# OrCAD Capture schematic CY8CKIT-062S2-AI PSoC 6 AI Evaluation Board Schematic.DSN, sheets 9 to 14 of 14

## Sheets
9 11. QSPI Memory and RADAR Snsr: size A4
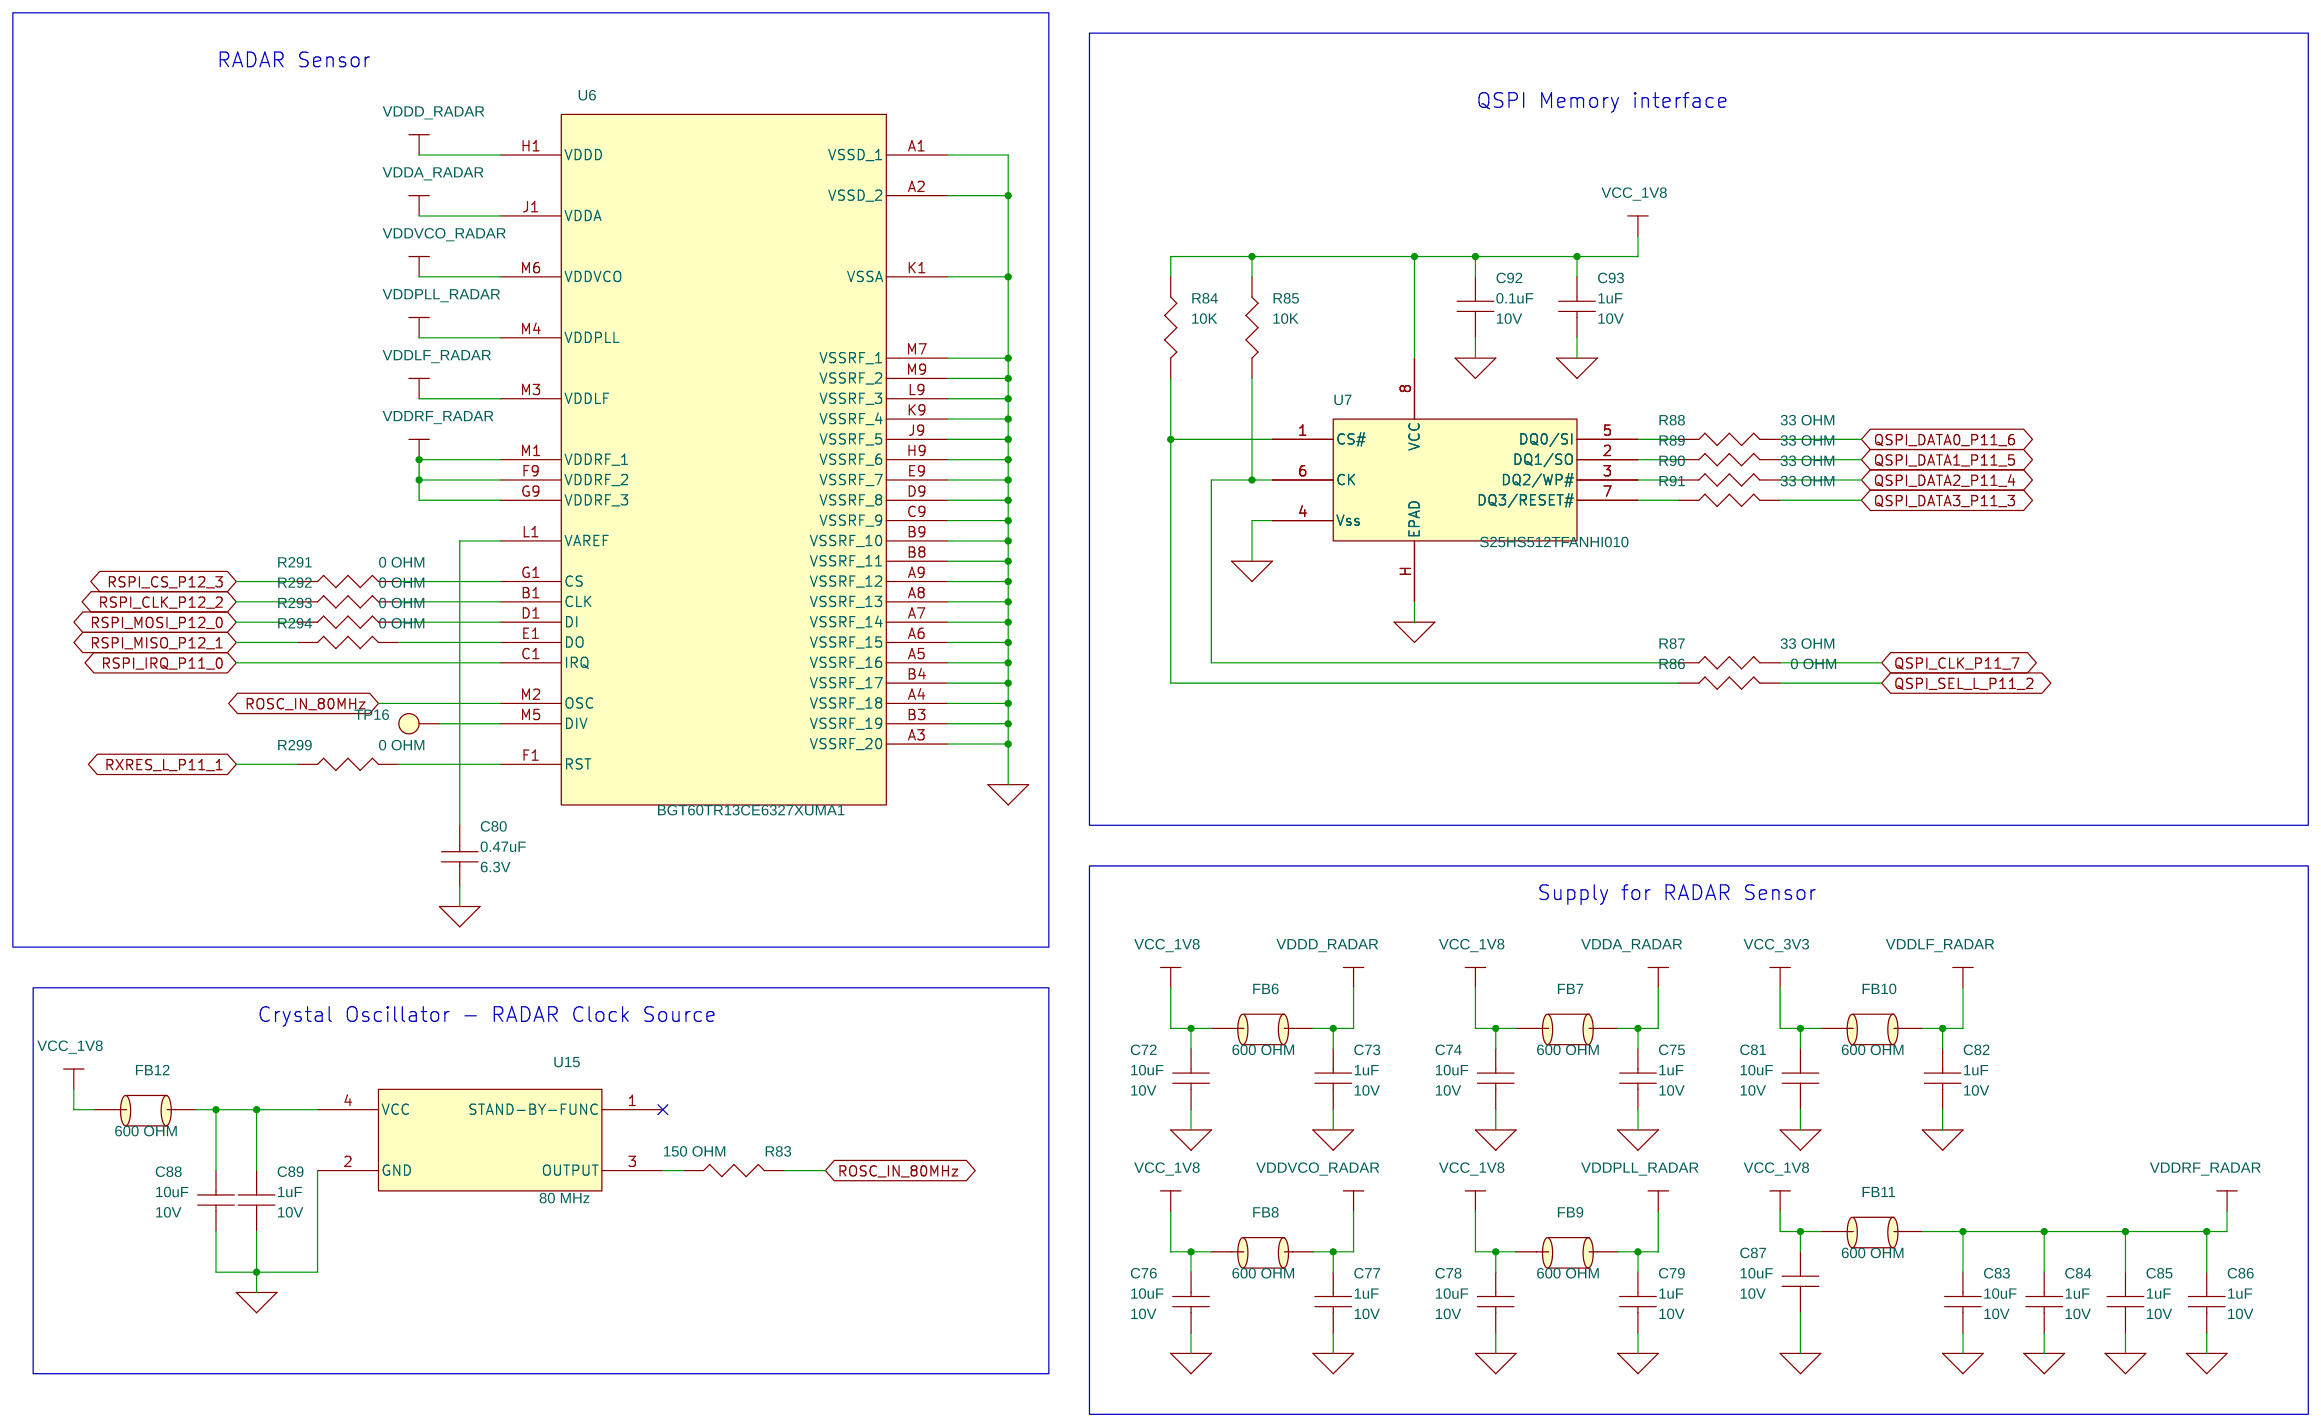
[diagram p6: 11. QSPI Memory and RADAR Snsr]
10 12.1YN Module Interface: size A4
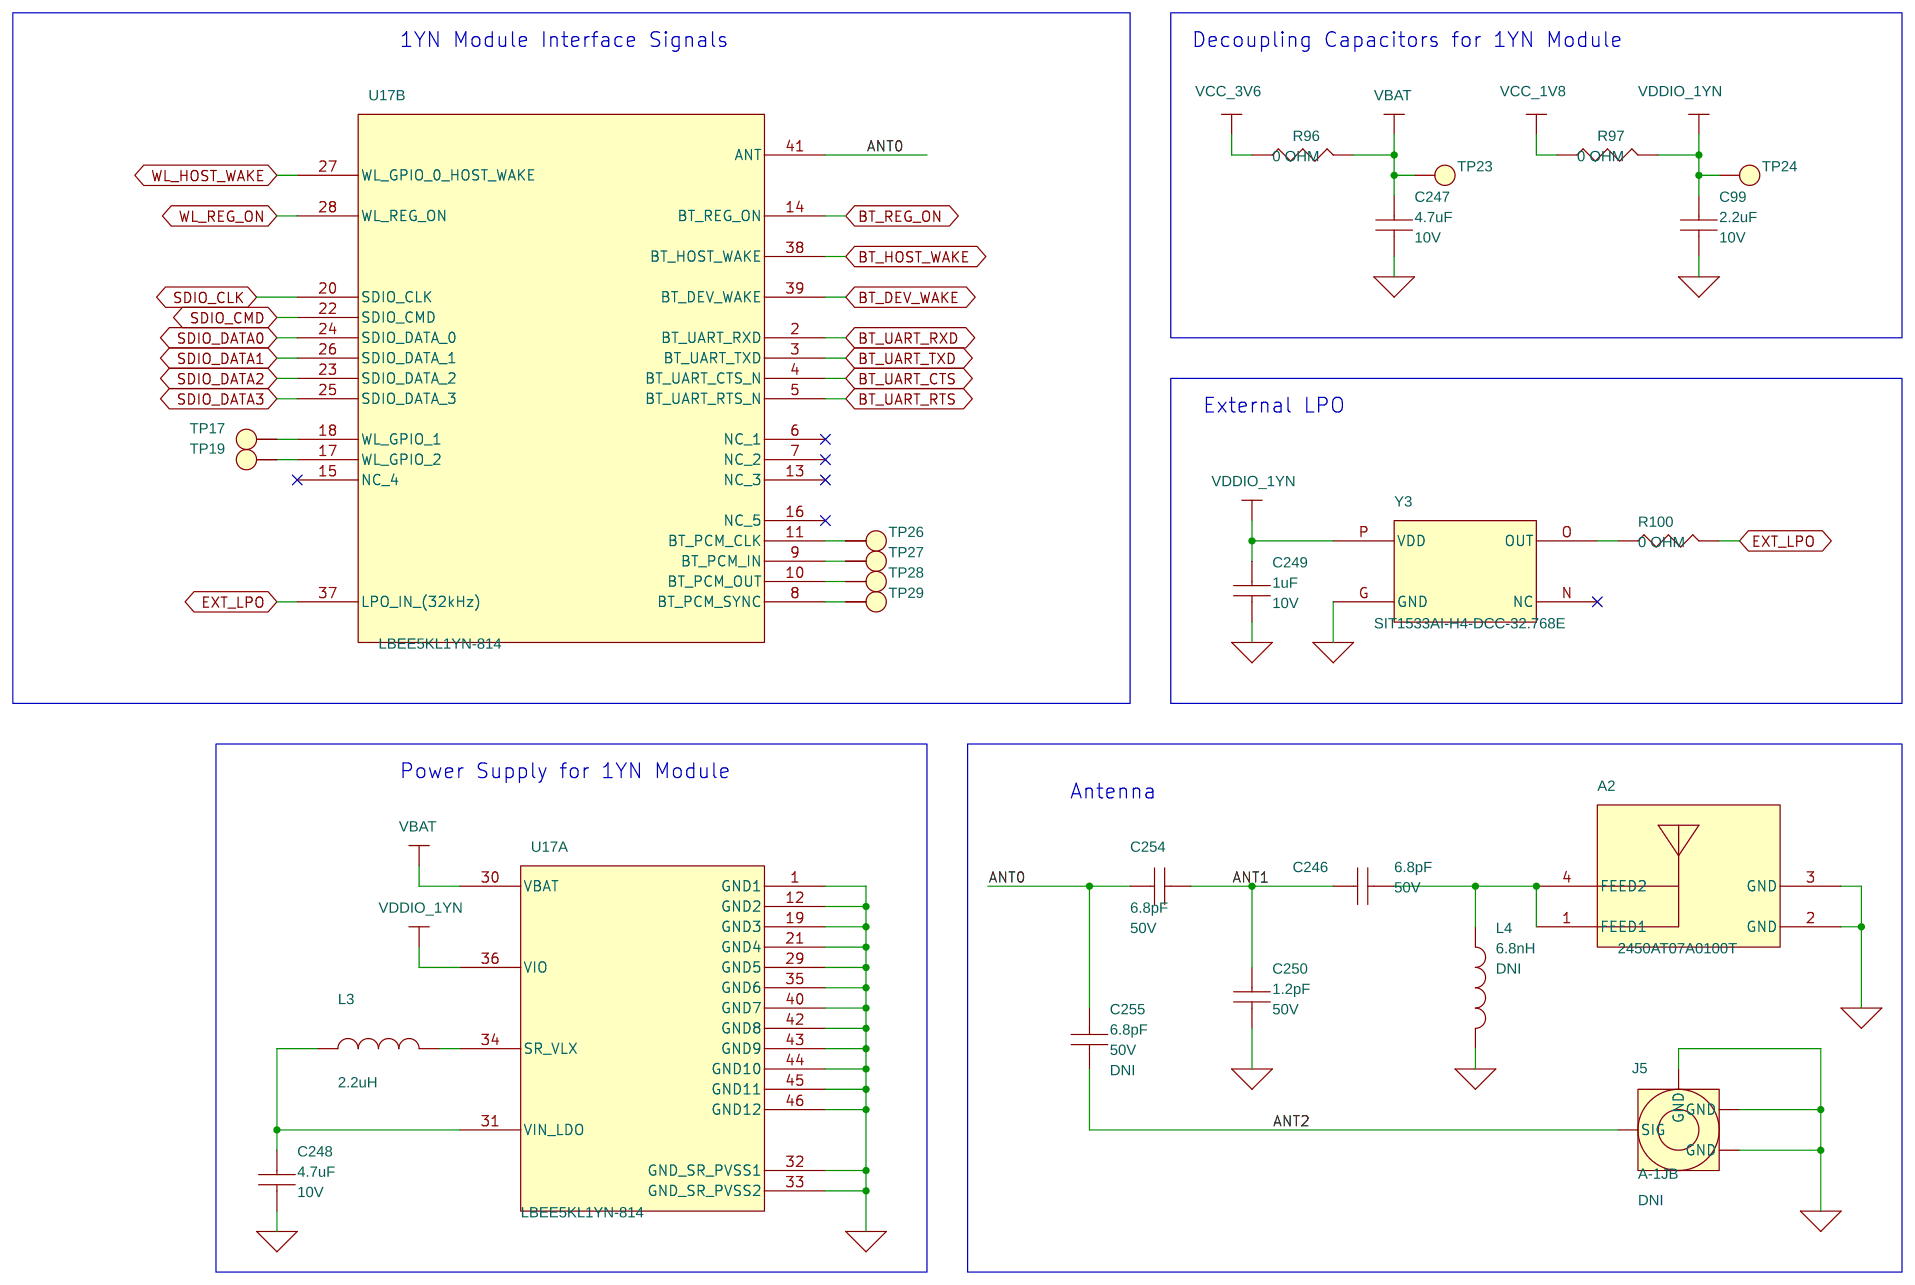
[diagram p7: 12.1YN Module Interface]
11 13. IO Expansion connectors: size A4
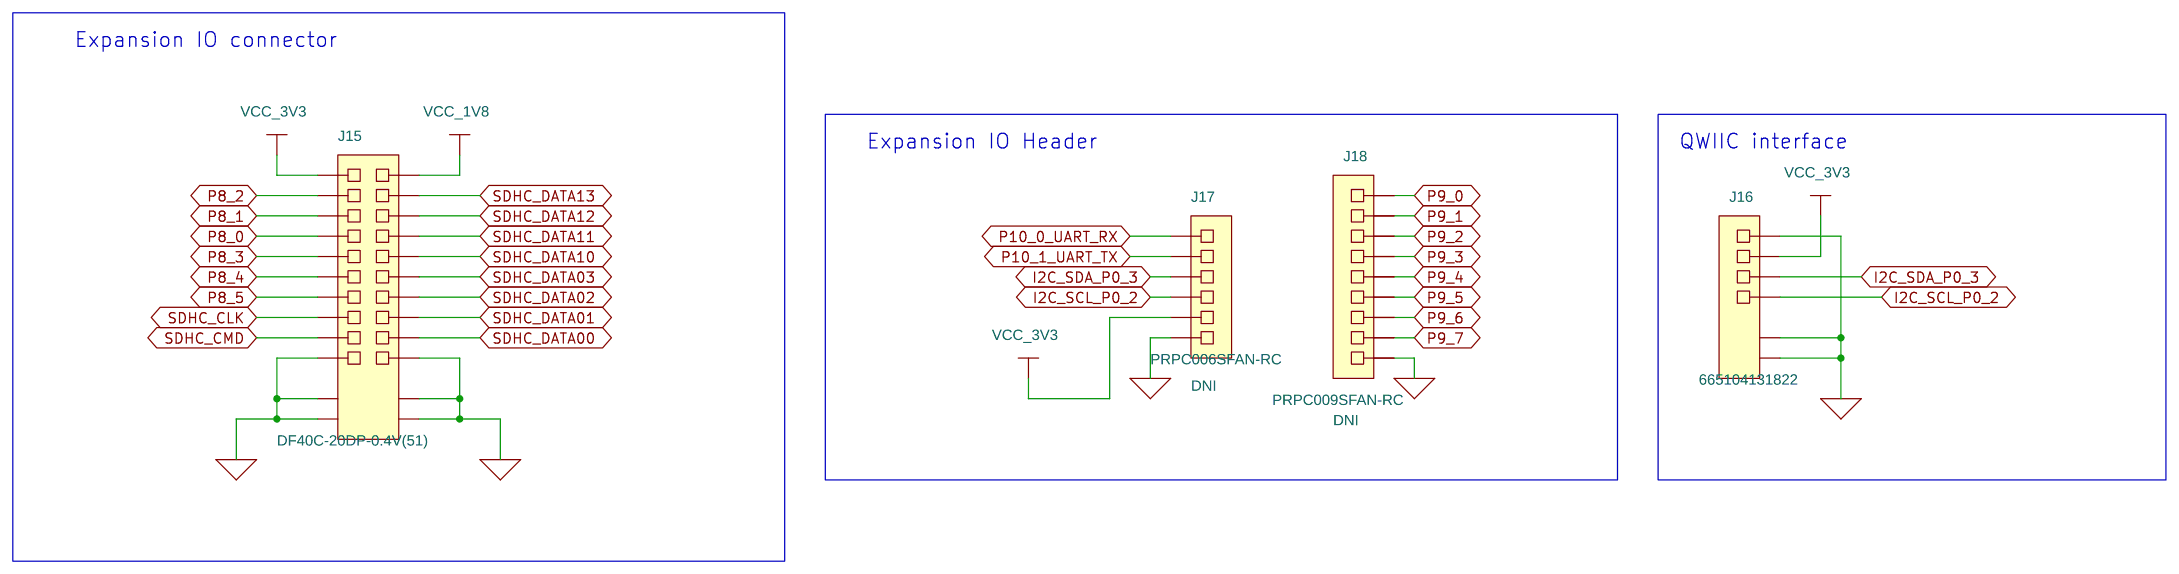
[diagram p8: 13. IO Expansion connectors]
12 14. Revision History
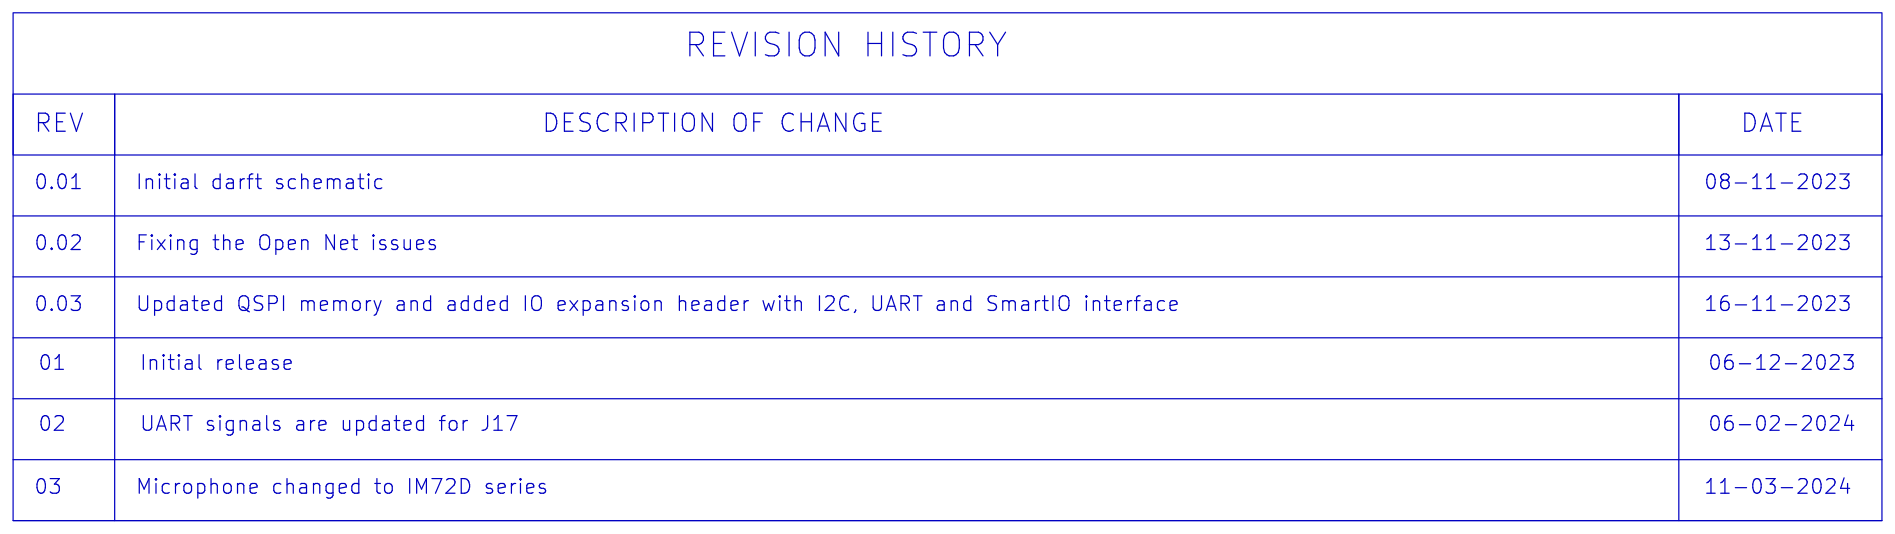
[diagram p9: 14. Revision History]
13 07. PSoC™ 6 Power: size A4
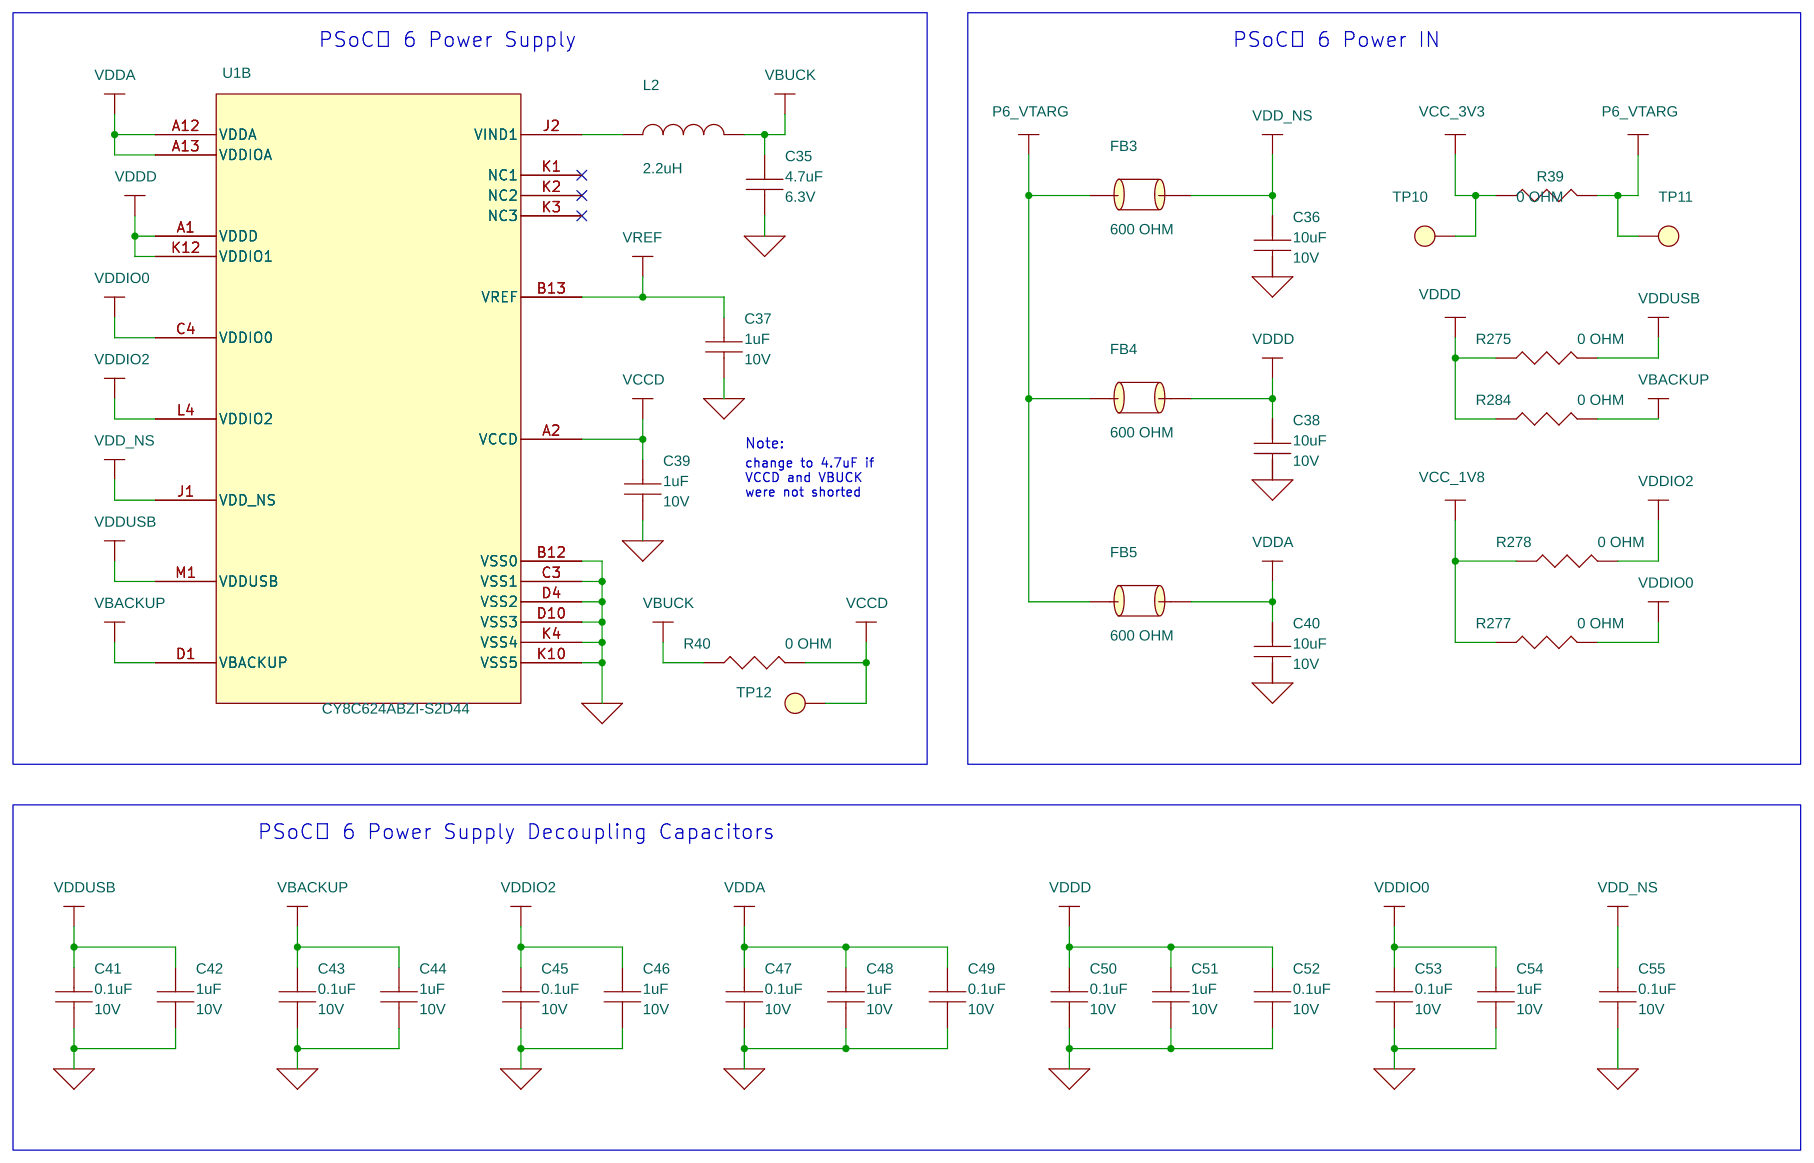
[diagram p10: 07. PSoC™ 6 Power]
14 08. PSoC™ 6 Signals: size A4
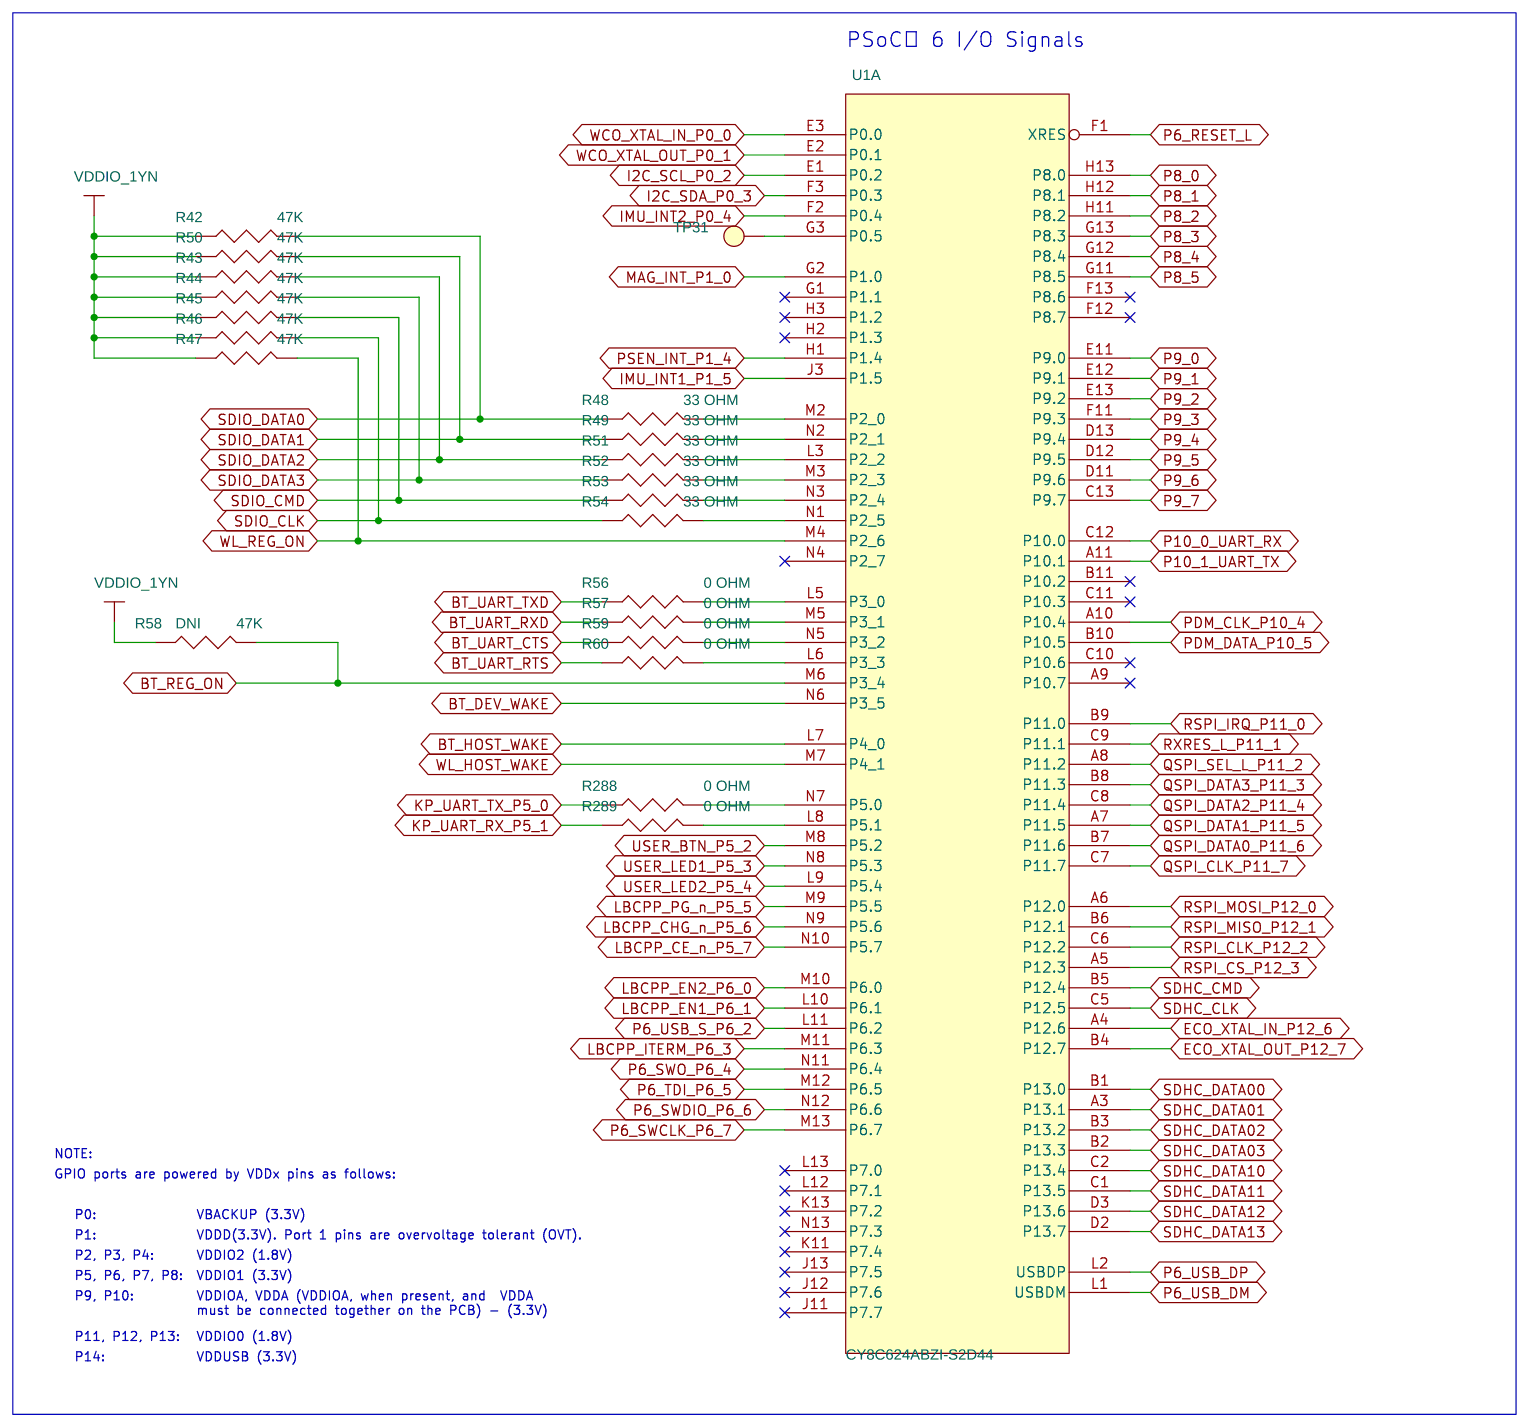
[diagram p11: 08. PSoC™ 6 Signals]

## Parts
sheet 07. PSoC™ 6 Power
C35  4.7uF  [CAPC0603_0201N]
C36  10uF  [CAPC1005_0402N]
C37  1uF  [CAPC0603_0201N]
C38  10uF  [CAPC1005_0402N]
C39  1uF  [CAPC0603_0201N]
C40  10uF  [CAPC1005_0402N]
C41  0.1uF  [CAPC0603_0201N]
C42  1uF  [CAPC0603_0201N]
C43  0.1uF  [CAPC0603_0201N]
C44  1uF  [CAPC0603_0201N]
C45  0.1uF  [CAPC0603_0201N]
C46  1uF  [CAPC0603_0201N]
C47  0.1uF  [CAPC0603_0201N]
C48  1uF  [CAPC0603_0201N]
C49  0.1uF  [CAPC0603_0201N]
C50  0.1uF  [CAPC0603_0201N]
C51  1uF  [CAPC0603_0201N]
C52  0.1uF  [CAPC0603_0201N]
C53  0.1uF  [CAPC0603_0201N]
C54  1uF  [CAPC0603_0201N]
C55  0.1uF  [CAPC0603_0201N]
FB3  600 OHM  [INDC1005_0402M]
FB4  600 OHM  [INDC1005_0402M]
FB5  600 OHM  [INDC1005_0402M]
L2  2.2uH  [INDC1608_0603N]
R39  0 OHM  [RESC1608_0603N]
R40  0 OHM  [RESC1005_0402N]
R275  0 OHM  [RESC1005_0402N]
R277  0 OHM  [RESC1005_0402N]
R278  0 OHM  [RESC1005_0402N]
R284  0 OHM  [RESC1005_0402N]
TP10  TP_SMD  [tp102c]
TP11  TP_SMD  [tp102c]
TP12  TP_SMD  [tp102c]
U1  CY8C624ABZI-S2D44  [BGA124C65P13X13_900X900X100]  (sections A,B)
sheet 08. PSoC™ 6 Signals
R42  47K  [RESC0603_0201N]
R43  47K  [RESC0603_0201N]
R44  47K  [RESC0603_0201N]
R45  47K  [RESC0603_0201N]
R46  47K  [RESC0603_0201N]
R47  47K  [RESC0603_0201N]
R48  33 OHM  [RESC0603_0201N]
R49  33 OHM  [RESC0603_0201N]
R50  47K  [RESC0603_0201N]
R51  33 OHM  [RESC0603_0201N]
R52  33 OHM  [RESC0603_0201N]
R53  33 OHM  [RESC0603_0201N]
R54  33 OHM  [RESC0603_0201N]
R56  0 OHM  [RESC1005_0402N]
R57  0 OHM  [RESC1005_0402N]
R58  47K  [RESC0603_0201N]
R59  0 OHM  [RESC1005_0402N]
R60  0 OHM  [RESC1005_0402N]
R288  0 OHM  [RESC1005_0402N]
R289  0 OHM  [RESC1005_0402N]
TP31  TP_SMD  [tp102c]
sheet 11. QSPI Memory and RADAR Snsr
C72  10uF  [CAPC1005_0402N]
C73  1uF  [CAPC0603_0201N]
C74  10uF  [CAPC1005_0402N]
C75  1uF  [CAPC0603_0201N]
C76  10uF  [CAPC1005_0402N]
C77  1uF  [CAPC0603_0201N]
C78  10uF  [CAPC1005_0402N]
C79  1uF  [CAPC0603_0201N]
C80  0.47uF  [CAPC1005_0402N]
C81  10uF  [CAPC1005_0402N]
C82  1uF  [CAPC0603_0201N]
C83  10uF  [CAPC1005_0402N]
C84  1uF  [CAPC0603_0201N]
C85  1uF  [CAPC0603_0201N]
C86  1uF  [CAPC0603_0201N]
C87  10uF  [CAPC1005_0402N]
C88  10uF  [CAPC1005_0402N]
C89  1uF  [CAPC0603_0201N]
C92  0.1uF  [CAPC0603_0201N]
C93  1uF  [CAPC0603_0201N]
FB6  600 OHM  [INDC1005_0402M]
FB7  600 OHM  [INDC1005_0402M]
FB8  600 OHM  [INDC1005_0402M]
FB9  600 OHM  [INDC1005_0402M]
FB10  600 OHM  [INDC1005_0402M]
FB11  600 OHM  [INDC1005_0402M]
FB12  600 OHM  [INDC1005_0402M]
R83  150 OHM  [RESC1005_0402N]
R84  10K  [RESC0603_0201N]
R85  10K  [RESC0603_0201N]
R86  0 OHM  [RESC0603_0201N]
R87  33 OHM  [RESC0603_0201N]
R88  33 OHM  [RESC0603_0201N]
R89  33 OHM  [RESC0603_0201N]
R90  33 OHM  [RESC0603_0201N]
R91  33 OHM  [RESC0603_0201N]
R291  0 OHM  [RESC0603_0201N]
R292  0 OHM  [RESC0603_0201N]
R293  0 OHM  [RESC0603_0201N]
R294  0 OHM  [RESC0603_0201N]
R299  0 OHM  [RESC0603_0201N]
TP16  TP_SMD  [tp102c]
U6  BGT60TR13CE6327XUMA1  [VF2BGA40N50P9X12_500X650X90]
U7  S25HS512TFANHI010  [SON127P800x600_8-H410x350]
U15  80 MHz  [OSCCC200X160X80-4N]
sheet 12.1YN Module Interface
A2  2450AT07A0100T  [ANT_2450AT07A0100]
C99  2.2uF  [CAPC1005_0402N]
C246  6.8pF  [CAPC1005_0402N]
C247  4.7uF  [CAPC1005_0402N]
C248  4.7uF  [CAPC1005_0402N]
C249  1uF  [CAPC0603_0201N]
C250  1.2pF  [CAPC1005_0402N]
C254  6.8pF  [CAPC1005_0402N]
C255  6.8pF  [CAPC1005_0402N]
J5  A-1JB  [AMP_A-1JB_ALT1]
L3  2.2uH  [INDC2012_0805N]
L4  6.8nH  [INDC1005_0402M]
R96  0 OHM  [RESC1608_0603N]
R97  0 OHM  [RESC1608_0603N]
R100  0 OHM  [RESC1005_0402N]
TP17  TP_SMD  [tp102c]
TP19  TP_SMD  [tp102c]
TP23  TP_SMD  [tp102c]
TP24  TP_SMD  [tp102c]
TP26  TP_SMD  [tp102c]
TP27  TP_SMD  [tp102c]
TP28  TP_SMD  [tp102c]
TP29  TP_SMD  [tp102c]
U17  LBEE5KL1YN-814  [MOD-LBEE5KL1DX_4343]  (sections A,B)
Y3  SIT1533AI-H4-DCC-32.768E  [OSSCCC200X120X55-4N]
sheet 13. IO Expansion connectors
J15  DF40C-20DP-0.4V(51)  [HIROSE_DF40C-20DP-0P4V]
J16  665104131822  [JST_SM04B-SRSS-TB]
J17  PRPC006SFAN-RC  [SULLINS_PRPC006SFAN-RC]
J18  PRPC009SFAN-RC  [SULLINS_PRPC009SFAN-RC]

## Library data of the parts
C35 = CAP-NP: CAP, CER, 4.7µF, ±20%, 6.3V, X5R, 0201; Approved: Approved; CY_PN: 510-61073-01; Device_File: 510-61073-01; Dielectric: X5R; FPLIST: CAPC0603_0201N,CAPC0603_0201Q; Lifecycle: Active; Manufacturer: Murata; Manufacturer_PN: GRM035R60J475ME15J; Operating_Temp: -55°C ~ 85°C; Package: 0201; Part_Status: In Prod; Tolerance: 20%; Voltage: 6.3V
C36 C38 C40 C72 C74 C76 C78 C81 C83 C87 C88 = CAP-NP: CAP, CER, 10uF, 20%, X5R, 10V, 0402; CY_PN: 510-60337-01; Device_File: 510-60337-01; Dielectric: X5R; FPLIST: CAPC1005_0402N,CAPC1005_0402M; Lifecycle: Active; Manufacturer: Samsung; Manufacturer_PN: CL05A106MP8NUB8; Operating_Temp: -55°C to 85°C; Package: 0402; Part_Status: In Prod; Tolerance: 20%; Voltage: 10V
C37 C39 C42 C44 C46 C48 C51 C54 C73 C75 C77 C79 C82 C84-C86 C89 C93 C249 = CAP-NP: CAP, CER, 1UF, 10V, X5R, 0201; Approved: Approved; CY_PN: 510-61118-01; Device_File: 510-61118-01; Dielectric: X5R; FPLIST: CAPC0603_0201N,CAPC0603_0201Q; Lifecycle: Active; Manufacturer: YAEGO; Manufacturer_PN: CC0201MRX5R6BB105; Operating_Temp: -55°C ~ 85°C; Package: 0201; Part_Status: In Prod; Tolerance: 20%; Voltage: 10V
C41 C43 C45 C47 C49 C50 C52 C53 C55 = CAP-NP: CAP, CER, 0.1uF, 20%, X5R, 10V, 0201; Approved: Approved; CY_PN: 510-60777-01; Device File: 510-60330-01; Device_File: 510-60777-01; Dielectric: X5R; FPLIST: CAPC0603_0201N,CAPC0603_0201Q; Lifecycle: Active; Manufacturer: Wurth; Manufacturer_PN: 885012104002; Operating_Temp: -55°C ~ 85°C; Package: 0201; Part Status: In Prod; Part_Status: In Prod; Tolerance: 20%; Voltage: 10V
FB3-FB12 = FB: IND, FERRITE BEAD, 600 OHM, 0402, 1LN; Approved: Approved; CY_PN: 520-60305-01; Current: 0.2A; DB_Status: Verified; Device_File: 520-60305-01; ESR: 850mOHM; FPLIST: INDC1005_0402M,INDC1005_0402N,INDC1005_0402L; Lifecycle: Active; Manufacturer: TDK; Manufacturer_PN: MMZ1005B601CT000; Material: Ferrite; Operating_Temp: -55°C ~ 125°C; Package: 0402; Part_Status: Unrel; Part_Type: Ferrite bead; Tolerance: NA
L2 = IND: IND, FIXED, SHIELDED, 2.2uH, 0.5A, 0.18 OHM, 0603; CY_PN: 520-60187-01; Current: 0.5A; DB_Status: Unverified; Device_File: 520-60187-01; ESR: 0.18 OHM; Lifecycle: Active; Manufacturer: TDK; Manufacturer_PN: MLZ1608N2R2LT000; Material: Ferrite; Operating_Temp: -55°C to 125°C; Package: 0603; Part_Status: In Prod; Part_Type: Inductor; Tolerance: 20%
R39 R96 R97 = RES: RES, Fixed, 0 OHM, JUMPER, 1A, 0603; CY_PN: 500-60037-01; Device_File: 500-60037-01; FPLIST: RESC1608_0603N,RESC1608_0603Q,RESC1608_0603M; Lifecycle: Active; Manufacturer: Panasonic; Manufacturer_PN: ERJ-3GEY0R00V; Operating_Temp: -55°C to 155°C; Package: 0603; Part_Status: In Production; Rating: 1A; Tolerance: JUMPER
R40 R56 R57 R59 R60 R100 R275 R277 R278 R284 R288 R289 = RES: RES, Fixed, 0 OHM, JUMPER, 1A, 0402; CY_PN: 500-60585-01; Device_File: 500-60585-01; FPLIST: RESC1005_0402N,RESC1005_0402M; Lifecycle: Active; Manufacturer: Yageo; Manufacturer_PN: RC0402JR-070RL; Operating_Temp: -55°C to 155°C; Package: 0402; Part_Status: In Production; Rating: 1A; Tolerance: JUMPER
TP10-TP12 TP16 TP17 TP19 TP23 TP24 TP26-TP29 TP31 = TP_SMD: TestPoint, PCB, Circle, 1mm, SMD; CY_PN: NA; DNI: DNI; Lifecycle: NA; Manufacturer: NA; Manufacturer_PN: NA; Part_Status: NA
U1 = CY8C624ABZI-S2D44: IC, CYPRESS, MCU, PSoC 62-S2, Dual Core, 150/100MHz, 1.71V-3.6V, 124-BGA; Description1: 1024KB SRAM, 2048KB Flash, 150/50MHz M4, 100/25MHz M0+, 100 GPIOs, CapSense, Crypto; FPLIST: BGA124C65P13X13_900X900X100,BGA124C65P13X13_900X900X100_NOFID; Lifecycle: Active; Manufacturer: Cypress; Operating_Temp: -40°C to 85°C; Operating_Voltage: 1.71V-3.6V; Package: 124-BGA; Part_Status: In Prod
R42-R47 R50 = RES: RES, Fixed, 47K, 5%, 1/20W, 0201; CY_PN: 500-60978-01; Device_File: 500-60978-01; FPLIST: RESC0603_0201N,RESC0603_0201Q; Lifecycle: Active; Manufacturer: Yageo; Manufacturer_PN: RC0201JR-0747KL; Operating_Temp: -55°C to 125°C; Package: 0201; Part_Status: In Production; Rating: 1/20W; Tolerance: 5%
R48 R49 R51-R54 R87-R91 = RES: RES, Fixed, 33 OHM, 5%, 1/20W, 0201; CY_PN: 500-60980-01; Device_File: 500-60980-01; FPLIST: RESC0603_0201N,RESC0603_0201Q; Lifecycle: Active; Manufacturer: Yageo; Manufacturer_PN: RC0201JR-0733RP; Operating_Temp: -55°C to 125°C; Package: 0201; Part_Status: In Production; Rating: 1/20W; SIGNAL_MODEL: DEFAULT_RESISTOR_33.000000OHM_1_2; Tolerance: 5%
R58 = RES: RES, Fixed, 47K, 5%, 1/20W, 0201; CY_PN: 500-60978-01; DNI: DNI; Device_File: 500-60978-01; FPLIST: RESC0603_0201N,RESC0603_0201Q; Lifecycle: Active; Manufacturer: Yageo; Manufacturer_PN: RC0201JR-0747KL; Operating_Temp: -55°C to 125°C; Package: 0201; Part_Status: In Production; Rating: 1/20W; Tolerance: 5%
C80 = CAP-NP: CAP, CER, 0.47UF, 20%, X5R, 6.3V, 0402; Approved: Approved; CY_PN: 510-61137-01; Device_File: 510-61137-01; Dielectric: X5R; FPLIST: CAPC1005_0402N,CAPC1005_0402M; Lifecycle: Active; Manufacturer: Wurth; Manufacturer_PN: 885012105004; Operating_Temp: -55°C ~ 85°C; Package: 0402; Part_Status: In Prod; Tolerance: 20%; Voltage: 6.3V
C92 = CAP-NP: CAP, CER, 0.1uF, 20%, X5R, 10V, 0201; Approved: Approved; CY_PN: 510-60777-01; Device_File: 510-60777-01; Dielectric: X5R; FPLIST: CAPC0603_0201N,CAPC0603_0201Q; Lifecycle: Active; Manufacturer: Wurth; Manufacturer_PN: 885012104002; Operating_Temp: -55°C ~ 85°C; Package: 0201; Part_Status: In Prod; Tolerance: 20%; Voltage: 10V
R83 = RES: RES, Fixed, 150 OHM, 1%, 1/10W, 0402; CY_PN: 500-60730-01; Device_File: 500-60730-01; FPLIST: RESC1005_0402N,RESC1005_0402M; Lifecycle: Active; Manufacturer: Panasonic; Manufacturer_PN: ERJ-2RKF1500X; Operating_Temp: -55°C to 155°C; Package: 0402; Part_Status: In Production; Rating: 1/10W; Tolerance: 1%
R84 R85 = RES: RES, 10K OHM, 1%, 1/20W, 0201; Approved: Approved; CY_PN: 500-61335-01; Device_File: 500-61335-01; FPLIST: RESC0603_0201N,RESC0603_0201Q; Lifecycle: Active; Manufacturer: Yageo; Manufacturer_PN: RC0201FR-0710KL; Operating_Temp: -55°C ~ 125°C; Package: 0201; Part_Status: Unrel; Rating: 1/20W; Tolerance: 1%
R86 R291-R294 R299 = RES: RES, Fixed, 0 OHM, JUMPER, 0.5A, 0201; CY_PN: 500-60684-01; Device File: 500-60037-01; Device_File: 500-60684-01; FPLIST: RESC0603_0201N,RESC0603_0201Q; Lifecycle: Active; Manufacturer: Yageo; Manufacturer_PN: RC0201JR-070RL; Operating_Temp: -55°C to 125°C; Package: 0201; Part_Status: In Production; Rating: 0.5A; Tolerance: JUMPER
U6 = IC_BGT60TR13C: IC, INFINEON, Radar Sensor, 60GHz, 1Tx 3Rx Antennas in Package, PG-VF2BGA40-1; Approved: Approved; Lifecycle: Active; Manufacturer: Infineon; Operating_Temp: -20 to +70°C; Operating_Voltage: 1.7V ~ 3.63V; Package: PG-VF2BGA40-1; Part_Status: Unrel
U7 = IC_S25HS512TFANH: IC, INFINEON, QSPI Flash, 1.8V IO, 166Mhz, 512Mb, WSON-8; Approved: Approved; Lifecycle: Active; Manufacturer: infineon; Operating_Temp: -40°C to 85°C; Operating_Voltage: 1.7 V to 2.0 V; Package: WSON-8; Part_Status: Unrel
U15 = OSC-KC2016K: OSC, 80MHz, 50PPM, 1.6/3.63V, SMD; Approved: Approved; CY_PN: 540-60028-01; Device_File: 540-60028-01; Lifecycle: Active; Load_Capacitance: NA; Manufacturer: KYOCERA; Manufacturer_PN: KC2016K80.0000C1GE00; Operating_Temp: -40°C ~ 85°C; Output_Type: CMOS; Package: SMD; Part_Status: Unrel; Supply_Voltage: 1.6V ~ 3.63V; Tolerance: 50ppm
A2 = ANT_2450AT07A0100: ANTENNA, CERAMIC CHIP, Single Band, 2.4GHz, SMD; Applications: WLAN, Bluetooth; Bands: 1; CY_PN: 753-60006-01; Description1: 2.4GHz - 2.5GHz, 1dBi Gain, 50 Ohm Impedance, 2W(max); Device_File: 753-60006-01; Frequency: 2.4GHz; Frequency_Range: 2.4GHz - 2.5GHz; Gain: 1dBi; Manufacturer: Johanson; Operating_Temp: -40°C to 125°C; Part_Status: In Des
C99 = CAP-NP: CAP CER 2.2UF 10V X5R 0402; Approved: Approved; CY_PN: 510-60376-01; Device_File: 510-60376-01; Dielectric: X5R; FPLIST: CAPC1005_0402N,CAPC1005_0402M; Lifecycle: Active; Manufacturer: Wurth; Manufacturer_PN: 885012105013; Operating_Temp: -55°C ~ 85°C; Package: 0402; Part_Status: In Prod; Tolerance: 20%; Voltage: 10V
C246 C254 = CAP-NP: CAP CER 6.8PF 50V C0G/NP0 0402; Approved: Approved; CY_PN: 510-60825-01; Device_File: 510-60825-01; Dielectric: COG/NPO; FPLIST: CAPC1005_0402N,CAPC1005_0402M; Lifecycle: Active; Manufacturer: Johanson; Manufacturer_PN: 500R07S6R8BV4T; Operating_Temp: -55°C ~ 125°C; Package: 0402; Part_Status: Unrel; Tolerance: 1.40%; Voltage: 50V
C247 C248 = CAP-NP: CAP, CER, 0402, 4.7uF, 20%, 10V, X5R; Approved: Approved; CY_PN: 510-60422-01; Device_File: 510-60422-01; Dielectric: X5R; FPLIST: CAPC1005_0402N,CAPC1005_0402M,capc1005_is0402q; Lifecycle: Active; Manufacturer: Murata; Manufacturer_PN: GRM155R61A475MEAAD; Operating_Temp: -55°C ~ 85°C; Package: 0402; Part_Status: Unrel; Tolerance: 20%; Voltage: 10V
C250 = CAP-NP: CAP, CER, 1.2PF, 8%, NP0, 50V, 0402; CY_PN: 510-60250-01; Description1: High Q, Low Loss; Device_File: 510-60250-01; Dielectric: NP0; FPLIST: CAPC1005_0402N,CAPC1005_0402M; Lifecycle: Active; Manufacturer: Johanson; Manufacturer_PN: 500R07S1R2BV4T; Operating_Temp: -55°C to 125°C; Package: 0402; Part_Status: In Prod; Tolerance: 8%; Voltage: 50V
C255 = CAP-NP: CAP CER 6.8PF 50V C0G/NP0 0402; Approved: Approved; CY_PN: 510-60825-01; DNI: DNI; Device_File: 510-60825-01; Dielectric: COG/NPO; FPLIST: CAPC1005_0402N,CAPC1005_0402M; Lifecycle: Active; Manufacturer: Johanson; Manufacturer_PN: 500R07S6R8BV4T; Operating_Temp: -55°C ~ 125°C; Package: 0402; Part_Status: Unrel; Tolerance: 1.40%; Voltage: 50V
J5 = A-1JB: CONN, UMC, JACK, STR, 50 OHM, SMD; CY_PN: 720-60585-01; Conatct_Length: NA; Contact_Finish: GOLD; Current_Rating: NA; DNI: DNI; Device_File: 720-60585-01; Lifecycle: Active; Manufacturer: Amphenol; Mated_Height: NA; Operating_Temp: -40°C to 90°C; Part_Status: Unrel; Pins: 4; Row_pitch: NA; Shrouding: NA
L3 = IND: IND, FIXED, SHIELDED, 2.2uH, 0.7A, 0.34 OHM, 0805; CY_PN: 520-60183-01; Current: 0.7A; DB_Status: Unverified; Device_File: 520-60183-01; ESR: 0.34 OHM; FPLIST: INDC2012_0805N,INDC2012_0805L; Lifecycle: Active; Manufacturer: Wurth; Manufacturer_PN: 74479774222; Material: Multilayer; Operating_Temp: -40°C to 125°C; Package: 0805; Part_Status: In Des; Part_Type: Inductor; Tolerance: 20%
L4 = IND: IND, FIXED, UNSHIELDED, 6.8nH, 0.25A, 0.32 OHM, 0402; Approved: Approved; CY_PN: 520-60020-01; Current: 0.25A; DB_Status: Unverified; DNI: DNI; Device_File: 520-60020-01; ESR: 0.32 OHM; FPLIST: INDC1005_0402M,INDC1005_0402N,INDC1005_0402L; Lifecycle: Active; Manufacturer: Johanson; Manufacturer_PN: L-07C6N8JV6T; Material: Ceramic; Operating_Temp: -40°C to 100°C; Package: 0402; Part_Status: In Prod; Part_Type: Inductor; Tolerance: 5%
U17 = LBEE5KL1DX: IC, Module, CYW43439, 2.4GHz WLAN + Bluetooth, SMD; Approved: Approved; CY_PN: 460-60009-01; Device_File: 460-60009-01; Lifecycle: Active; Manufacturer: Murata; Operating_Temp: -30? to 70?; Operating_Voltage: 3.2V to 4.2V; Package: LGA; Part_Status: Unrel
Y3 = OSC-SiT1533: OSC, MEMS, 32.768kHz, 20ppm, LVCMOS, SMD; CY_PN: 540-60011-01; Description1: 2.00mm x 1.20mm x 0.55mm; Device_File: 540-60011-01; FPLIST: OSSCCC200X120X55-4N,OSCS4_SIT_2M0X1M2SPL_NGOPQ; Frequency_Stability: 20ppm; Lifecycle: Active; Load_Capacitance: NA; Manufacturer: SiTIME; Operating_Temp: -40°C to 85°C; Output_Type: LVCMOS; Package: SMD; Part_Status: In Des; Supply_Voltage: 1.2V - 3.63V; Tolerance: NA
J15 = PLG-20-ODD-EVEN-4SH-J: CONN, PLUG, DUAL, 20POS, 0.4mm, SMD, GOLD; Approved: Approved; CY_PN: 720-60640-01; Conatct_Length: 0.45mm; Contact_Finish: GOLD; Current_Rating: 0.3A; Device_File: 720-60640-01; Lifecycle: Active; Manufacturer: Hirose; Mated_Height: 1.5mm; Operating_Temp: -35°C ~ +85°C; Part_Status: Unrel; Pin_Pitch: 0.4mm; Pins: 20; Row_pitch: 3.8mm; Rows: 2; Shrouding: Shrouded
J16 = PLG-4-2SH-J: CONN, HEADER, R/A, 4POS, 1MM, SMD; Approved: Approved; CY_PN: 720-60696-01; Conatct_Length: NA; Contact_Finish: Tin; Current_Rating: 1A; Device_File: 720-60696-01; Lifecycle: Active; Manufacturer: Wurth; Mated_Height: NA; Operating_Temp: -25°C ~ 85°C; Part_Status: In Des; Pin_Pitch: 1mm; Pins: 4; Row_pitch: NA; Rows: 1; Shrouding: Shrouded
J17 = PLG-6-J: CONN, HEADER, VERT, 6POS, 2.54MM, TH; Approved: Approved; CY_PN: 710-60054-01; Conatct_Length: 8.08mm; Contact_Finish: GOLD; Current_Rating: 3A; DNI: DNI; Device_File: 710-60054-01; Lifecycle: Active; Manufacturer: Sullins; Mated_Height: 10.58mm; Operating_Temp: -40°C ~ 105°C; Part_Status: Unrel; Pin_Pitch: 2.54mm; Pins: 6; Row_pitch: NA; Rows: 1; Shrouding: Unshrouded
J18 = PLG-9-J: CONN, HEADER, VERT, 9POS, 2.54MM, TH; Approved: Approved; CY_PN: 710-60142-01; Conatct_Length: 8.08mm; Contact_Finish: GOLD; Current_Rating: 3A; DNI: DNI; Device_File: 710-60142-01; Lifecycle: Active; Manufacturer: Sullins; Mated_Height: 10.58mm; Operating_Temp: -40°C ~ 105°C; Part_Status: Unrel; Pin_Pitch: 2.54mm; Pins: 9; Row_pitch: NA; Rows: 1; Shrouding: Unshrouded

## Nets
GND_SIGNAL: A2.2(GND) A2.3(GND) C35.2 C36.2 C37.2 C38.2 C39.2 C40.2 C41.2 C42.2 C43.2 C44.2 C45.2 C46.2 C47.2 C48.2 C49.2 C50.2 C51.2 C52.2 C53.2 C54.2 C55.2 C72.2 C73.2 C74.2 C75.2 C76.2 C77.2 C78.2 C79.2 C80.1 C81.2 C82.2 C83.2 C84.2 C85.2 C86.2 C87.2 C88.2 C89.2 C92.2 C93.2 C99.2 C247.2 C248.2 C249.2 C250.2 J5.G1(GND) J5.G2(GND) J5.G3(GND) J15.19 J15.20 J15.SH1 J15.SH2 J15.SH3 J15.SH4 J16.1 J16.SH1 J16.SH2 J17.6 J18.9 L4.2 U1.B12(VSS0) U1.C3(VSS1) U1.D4(VSS2) U1.D10(VSS3) U1.K4(VSS4) U1.K10(VSS5) U6.A1(VSSD_1) U6.A2(VSSD_2) U6.A3(VSSRF_20) U6.A4(VSSRF_18) U6.A5(VSSRF_16) U6.A6(VSSRF_15) U6.A7(VSSRF_14) U6.A8(VSSRF_13) U6.A9(VSSRF_12) U6.B3(VSSRF_19) U6.B4(VSSRF_17) U6.B8(VSSRF_11) U6.B9(VSSRF_10) U6.C9(VSSRF_9) U6.D9(VSSRF_8) U6.E9(VSSRF_7) U6.H9(VSSRF_6) U6.J9(VSSRF_5) U6.K1(VSSA) U6.K9(VSSRF_4) U6.L9(VSSRF_3) U6.M7(VSSRF_1) U6.M9(VSSRF_2) U7.4(Vss) U7.H(EPAD) U15.2(GND) U17.1(GND1) U17.12(GND2) U17.19(GND3) U17.21(GND4) U17.29(GND5) U17.32(GND_SR_PVSS1) U17.33(GND_SR_PVSS2) U17.35(GND6) U17.40(GND7) U17.42(GND8) U17.43(GND9) U17.44(GND10) U17.45(GND11) U17.46(GND12) Y3.G(GND) ; also on sheet 4 5 6 7 8
VBAT: C247.1 R96.2 TP23.1(TP) U17.30(VBAT)
VCC_1V8: C72.1 C74.1 C76.1 C78.1 C87.1 C92.1 C93.1 FB6.1 FB7.1 FB8.1 FB9.1 FB11.1 FB12.1 J15.2 R84.1 R85.1 R97.1 R277.1 R278.1 U7.8(VCC) ; also on sheet 5 7
VCC_3V3: C81.1 FB10.1 J15.1 J16.2 J17.5 R39.1 TP10.1(TP) ; also on sheet 5 7
VCC_3V6: R96.1 ; also on sheet 5
VCCD: C39.1 R40.2 TP12.1(TP) U1.A2(VCCD)
VDD_NS: C36.1 C55.1 FB3.1 U1.J1(VDD_NS)
VDDA: C40.1 C47.1 C48.1 C49.1 FB5.1 U1.A12(VDDA) U1.A13(VDDIOA)
VDDA_RADAR: C75.1 FB7.2 U6.J1(VDDA)
VDDD: C38.1 C50.1 C51.1 C52.1 FB4.1 R275.1 R284.1 U1.A1(VDDD) U1.K12(VDDIO1) ; also on sheet 8
VDDD_RADAR: C73.1 FB6.2 U6.H1(VDDD)
VDDIO0: C53.1 C54.1 R277.2 U1.C4(VDDIO0)
VDDIO2: C45.1 C46.1 R278.2 U1.L4(VDDIO2)
VDDIO_1YN: C99.1 C249.1 R42.1 R43.1 R44.1 R45.1 R46.1 R47.1 R50.1 R58.1 R97.2 TP24.1(TP) U17.36(VIO) Y3.P(VDD)
VDDLF_RADAR: C82.1 FB10.2 U6.M3(VDDLF)
VDDPLL_RADAR: C79.1 FB9.2 U6.M4(VDDPLL)
VDDRF_RADAR: C83.1 C84.1 C85.1 C86.1 FB11.2 U6.F9(VDDRF_2) U6.G9(VDDRF_3) U6.M1(VDDRF_1)
VDDUSB: C41.1 C42.1 R275.2 U1.M1(VDDUSB)
VDDVCO_RADAR: C77.1 FB8.2 U6.M6(VDDVCO)
ANT0: C254.1 C255.2 U17.41(ANT)
ANT1: C246.1 C250.1 C254.2
ANT2: C255.1 J5.S(SIG)
BT_DEV_WAKE: U1.N6(P3_5) U17.39(BT_DEV_WAKE)
BT_HOST_WAKE: U1.L7(P4_0) U17.38(BT_HOST_WAKE)
BT_REG_ON: R58.2 U1.M6(P3_4) U17.14(BT_REG_ON)
BT_UART_CTS: R59.1 U17.4(BT_UART_CTS_N)
BT_UART_RTS: R60.1 U17.5(BT_UART_RTS_N)
BT_UART_RXD: R57.1 U17.2(BT_UART_RXD)
BT_UART_TXD: R56.1 U17.3(BT_UART_TXD)
ECO_XTAL_IN_P12_6: U1.A4(P12.6) ; also on sheet 8
ECO_XTAL_OUT_P12_7: U1.B4(P12.7) ; also on sheet 8
EXT_LPO: R100.2 U17.37(LPO_IN_(32kHz))
I2C_SCL_P0_2: J16.4 J17.4 U1.E1(P0.2) ; also on sheet 6 7
I2C_SDA_P0_3: J16.3 J17.3 U1.F3(P0.3) ; also on sheet 6 7
IMU_INT1_P1_5: U1.J3(P1.5) ; also on sheet 7
IMU_INT2_P0_4: U1.F2(P0.4) ; also on sheet 7
KP_UART_RX_P5_1: R289.1 ; also on sheet 6
KP_UART_TX_P5_0: R288.1 ; also on sheet 6
LBCPP_CE_n_P5_7: U1.N10(P5.7) ; also on sheet 4
LBCPP_CHG_n_P5_6: U1.N9(P5.6) ; also on sheet 4
LBCPP_EN1_P6_1: U1.L10(P6.1) ; also on sheet 4
LBCPP_EN2_P6_0: U1.M10(P6.0) ; also on sheet 4
LBCPP_ITERM_P6_3: U1.M11(P6.3) ; also on sheet 4
LBCPP_PG_n_P5_5: U1.M9(P5.5) ; also on sheet 4
MAG_INT_P1_0: U1.G2(P1.0) ; also on sheet 7
P6_RESET_L: U1.F1(XRES) ; also on sheet 6 8
P6_SWCLK_P6_7: U1.M13(P6.7) ; also on sheet 6 8
P6_SWDIO_P6_6: U1.N12(P6.6) ; also on sheet 6 8
P6_SWO_P6_4: U1.N11(P6.4) ; also on sheet 8
P6_TDI_P6_5: U1.M12(P6.5) ; also on sheet 8
P6_USB_DM: U1.L1(USBDM) ; also on sheet 4
P6_USB_DP: U1.L2(USBDP) ; also on sheet 4
P6_USB_S_P6_2: U1.L11(P6.2) ; also on sheet 4
P6_VTARG: FB3.2 FB4.2 FB5.2 R39.2 TP11.1(TP) ; also on sheet 6 8
P8_0: J15.7 U1.H13(P8.0)
P8_1: J15.5 U1.H12(P8.1)
P8_2: J15.3 U1.H11(P8.2)
P8_3: J15.9 U1.G13(P8.3)
P8_4: J15.11 U1.G12(P8.4)
P8_5: J15.13 U1.G11(P8.5)
P9_0: J18.1 U1.E11(P9.0)
P9_1: J18.2 U1.E12(P9.1)
P9_2: J18.3 U1.E13(P9.2)
P9_3: J18.4 U1.F11(P9.3)
P9_4: J18.5 U1.D13(P9.4)
P9_5: J18.6 U1.D12(P9.5)
P9_6: J18.7 U1.D11(P9.6)
P9_7: J18.8 U1.C13(P9.7)
P10_0_UART_RX: J17.1 U1.C12(P10.0)
P10_1_UART_TX: J17.2 U1.A11(P10.1)
PDM_CLK_P10_4: U1.A10(P10.4) ; also on sheet 7
PDM_DATA_P10_5: U1.B10(P10.5) ; also on sheet 7
PSEN_INT_P1_4: U1.H1(P1.4) ; also on sheet 7
QSPI_CLK_P11_7: R87.2 U1.C7(P11.7)
QSPI_DATA0_P11_6: R88.2 U1.B7(P11.6)
QSPI_DATA1_P11_5: R89.2 U1.A7(P11.5)
QSPI_DATA2_P11_4: R90.2 U1.C8(P11.4)
QSPI_DATA3_P11_3: R91.2 U1.B8(P11.3)
QSPI_SEL_L_P11_2: R86.2 U1.A8(P11.2)
ROSC_IN_80MHz: R83.2 U6.M2(OSC)
RSPI_CLK_P12_2: R292.1 U1.C6(P12.2)
RSPI_CS_P12_3: R291.1 U1.A5(P12.3)
RSPI_IRQ_P11_0: U1.B9(P11.0) U6.C1(IRQ)
RSPI_MISO_P12_1: R294.1 U1.B6(P12.1)
RSPI_MOSI_P12_0: R293.1 U1.A6(P12.0)
RXRES_L_P11_1: R299.1 U1.C9(P11.1)
SDHC_CLK: J15.15 U1.C5(P12.5)
SDHC_CMD: J15.17 U1.B5(P12.4)
SDHC_DATA00: J15.18 U1.B1(P13.0)
SDHC_DATA01: J15.16 U1.A3(P13.1)
SDHC_DATA02: J15.14 U1.B3(P13.2)
SDHC_DATA03: J15.12 U1.B2(P13.3)
SDHC_DATA10: J15.10 U1.C2(P13.4)
SDHC_DATA11: J15.8 U1.C1(P13.5)
SDHC_DATA12: J15.6 U1.D3(P13.6)
SDHC_DATA13: J15.4 U1.D2(P13.7)
SDIO_CLK: R46.2 R54.1 U17.20(SDIO_CLK)
SDIO_CMD: R45.2 R53.1 U17.22(SDIO_CMD)
SDIO_DATA0: R42.2 R48.1 U17.24(SDIO_DATA_0)
SDIO_DATA1: R49.1 R50.2 U17.26(SDIO_DATA_1)
SDIO_DATA2: R43.2 R51.1 U17.23(SDIO_DATA_2)
SDIO_DATA3: R44.2 R52.1 U17.25(SDIO_DATA_3)
USER_BTN_P5_2: U1.M8(P5.2) ; also on sheet 8
USER_LED1_P5_3: U1.N8(P5.3) ; also on sheet 8
USER_LED2_P5_4: U1.L9(P5.4) ; also on sheet 8
VBACKUP: C43.1 C44.1 R284.2 U1.D1(VBACKUP)
VBUCK: C35.1 L2.2 R40.1
VREF: C37.1 U1.B13(VREF)
WCO_XTAL_IN_P0_0: U1.E3(P0.0) ; also on sheet 8
WCO_XTAL_OUT_P0_1: U1.E2(P0.1) ; also on sheet 8
WL_HOST_WAKE: U1.M7(P4_1) U17.27(WL_GPIO_0_HOST_WAKE)
WL_REG_ON: R47.2 U1.M4(P2_6) U17.28(WL_REG_ON)
N17065875: L2.1 U1.J2(VIND1)
N17073640: R48.2 U1.M2(P2_0)
N17073643: R49.2 U1.N2(P2_1)
N17073646: R51.2 U1.L3(P2_2)
N17073649: R52.2 U1.M3(P2_3)
N17073652: R53.2 U1.N3(P2_4)
N17073655: R54.2 U1.N1(P2_5)
N17076511: R56.2 U1.L5(P3_0)
N17076512: R57.2 U1.M5(P3_1)
N17076513: R60.2 U1.L6(P3_3)
N17076514: R59.2 U1.N5(P3_2)
N17289581: R88.1 U7.5(DQ0/SI)
N17289597: R89.1 U7.2(DQ1/SO)
N17289613: R90.1 U7.3(DQ2/WP#)
N17289629: R91.1 U7.7(DQ3/RESET#)
N17305257: C248.1 L3.1 U17.31(VIN_LDO)
N17305261: L3.2 U17.34(SR_VLX)
N17332525: A2.1(FEED1) A2.4(FEED2) C246.2 L4.1
N17332695: TP17.1(TP) U17.18(WL_GPIO_1)
N17332709: TP19.1(TP) U17.17(WL_GPIO_2)
N17332795: TP28.1(TP) U17.10(BT_PCM_OUT)
N17459450: R100.1 Y3.O(OUT)
N17461053: TP16.1(TP) U6.M5(DIV)
N17461288: C80.2 U6.L1(VAREF)
N17462113: C88.1 C89.1 FB12.2 U15.4(VCC)
N17462137: R83.1 U15.3(OUTPUT)
N17505741: TP29.1(TP) U17.8(BT_PCM_SYNC)
N17505744: TP27.1(TP) U17.9(BT_PCM_IN)
N17505747: TP26.1(TP) U17.11(BT_PCM_CLK)
N17531797: R84.2 R86.1 U7.1(CS#)
N17531826: R85.2 R87.1 U7.6(CK)
N17592490: R288.2 U1.N7(P5.0)
N17592497: R289.2 U1.L8(P5.1)
N17595841: R294.2 U6.E1(DO)
N17595844: R293.2 U6.D1(DI)
N17595847: R292.2 U6.B1(CLK)
N17595850: R291.2 U6.G1(CS)
N17604769: R299.2 U6.F1(RST)
N17607574: TP31.1(TP) U1.G3(P0.5)

Not connected (* = marked no-connect by the designer): U1 A9(P10.7)* B11(P10.2)* C10(P10.6)* C11(P10.3)* F12(P8.7)* F13(P8.6)* G1(P1.1)* H2(P1.3)* H3(P1.2)* J11(P7.7)* J12(P7.6)* J13(P7.5)* K1(NC1)* K2(NC2)* K3(NC3)* K11(P7.4)* K13(P7.2)* L12(P7.1)* L13(P7.0)* N4(P2_7)* N13(P7.3)*; U15 1(STAND-BY-FUNC)*; U17 6(NC_1)* 7(NC_2)* 13(NC_3)* 15(NC_4)* 16(NC_5)*; Y3 N(NC)*

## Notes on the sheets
sheet 9
- RADAR Sensor
- QSPI Memory interface
- Supply for RADAR Sensor
- Crystal Oscillator - RADAR Clock Source
sheet 10
- 1YN Module Interface Signals
- Decoupling Capacitors for 1YN Module
- External LPO
- Power Supply for 1YN Module
- Antenna
sheet 11
- Expansion IO connector
- Expansion IO Header
- QWIIC interface
sheet 12
- REVISION HISTORY
- REV
- DESCRIPTION OF CHANGE
- DATE
- 0.01
- Initial darft schematic
- 08-11-2023
- 0.02
- Fixing the Open Net issues
- 13-11-2023
- 0.03
- Updated QSPI memory and added IO expansion header with I2C, UART and SmartIO interface
- 16-11-2023
- 01
- Initial release
- 06-12-2023
- 02
- UART signals are updated for J17
- 06-02-2024
- 03
- Microphone changed to IM72D series
- 11-03-2024
sheet 13
- PSoC™ 6 Power Supply
- PSoC™ 6 Power IN
- Note:
- change to 4.7uF if
  VCCD and VBUCK
  were not shorted
- PSoC™ 6 Power Supply Decoupling Capacitors
sheet 14
- PSoC™ 6 I/O Signals
- NOTE:
- GPIO ports are powered by VDDx pins as follows:
- P0:
- VBACKUP (3.3V)
- P1:
- VDDD(3.3V). Port 1 pins are overvoltage tolerant (OVT).
- P2, P3, P4:
- VDDIO2 (1.8V)
- P5, P6, P7, P8:
- P9, P10:
- VDDIO1 (3.3V)
- VDDIOA, VDDA (VDDIOA, when present, and  VDDA
  must be connected together on the PCB) - (3.3V)
- P11, P12, P13:
- VDDIO0 (1.8V)
- P14:
- VDDUSB (3.3V)
